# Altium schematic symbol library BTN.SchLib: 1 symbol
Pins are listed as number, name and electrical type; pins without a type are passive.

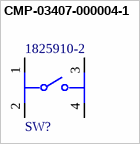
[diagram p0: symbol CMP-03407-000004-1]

## CMP-03407-000004-1
designator SW?, comment 1825910-2
SWITCH TACTILE SPST-NO 0.05A 24V; Manufacturer: TE; Contact Current Rating: 50mA; Operating Force: 160gf; Contact Resistance: 100mΩ; Electromechanical Life: 100000Cycles
footprint FP-1825910-2-0
pins: 1, 2, 3, 4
